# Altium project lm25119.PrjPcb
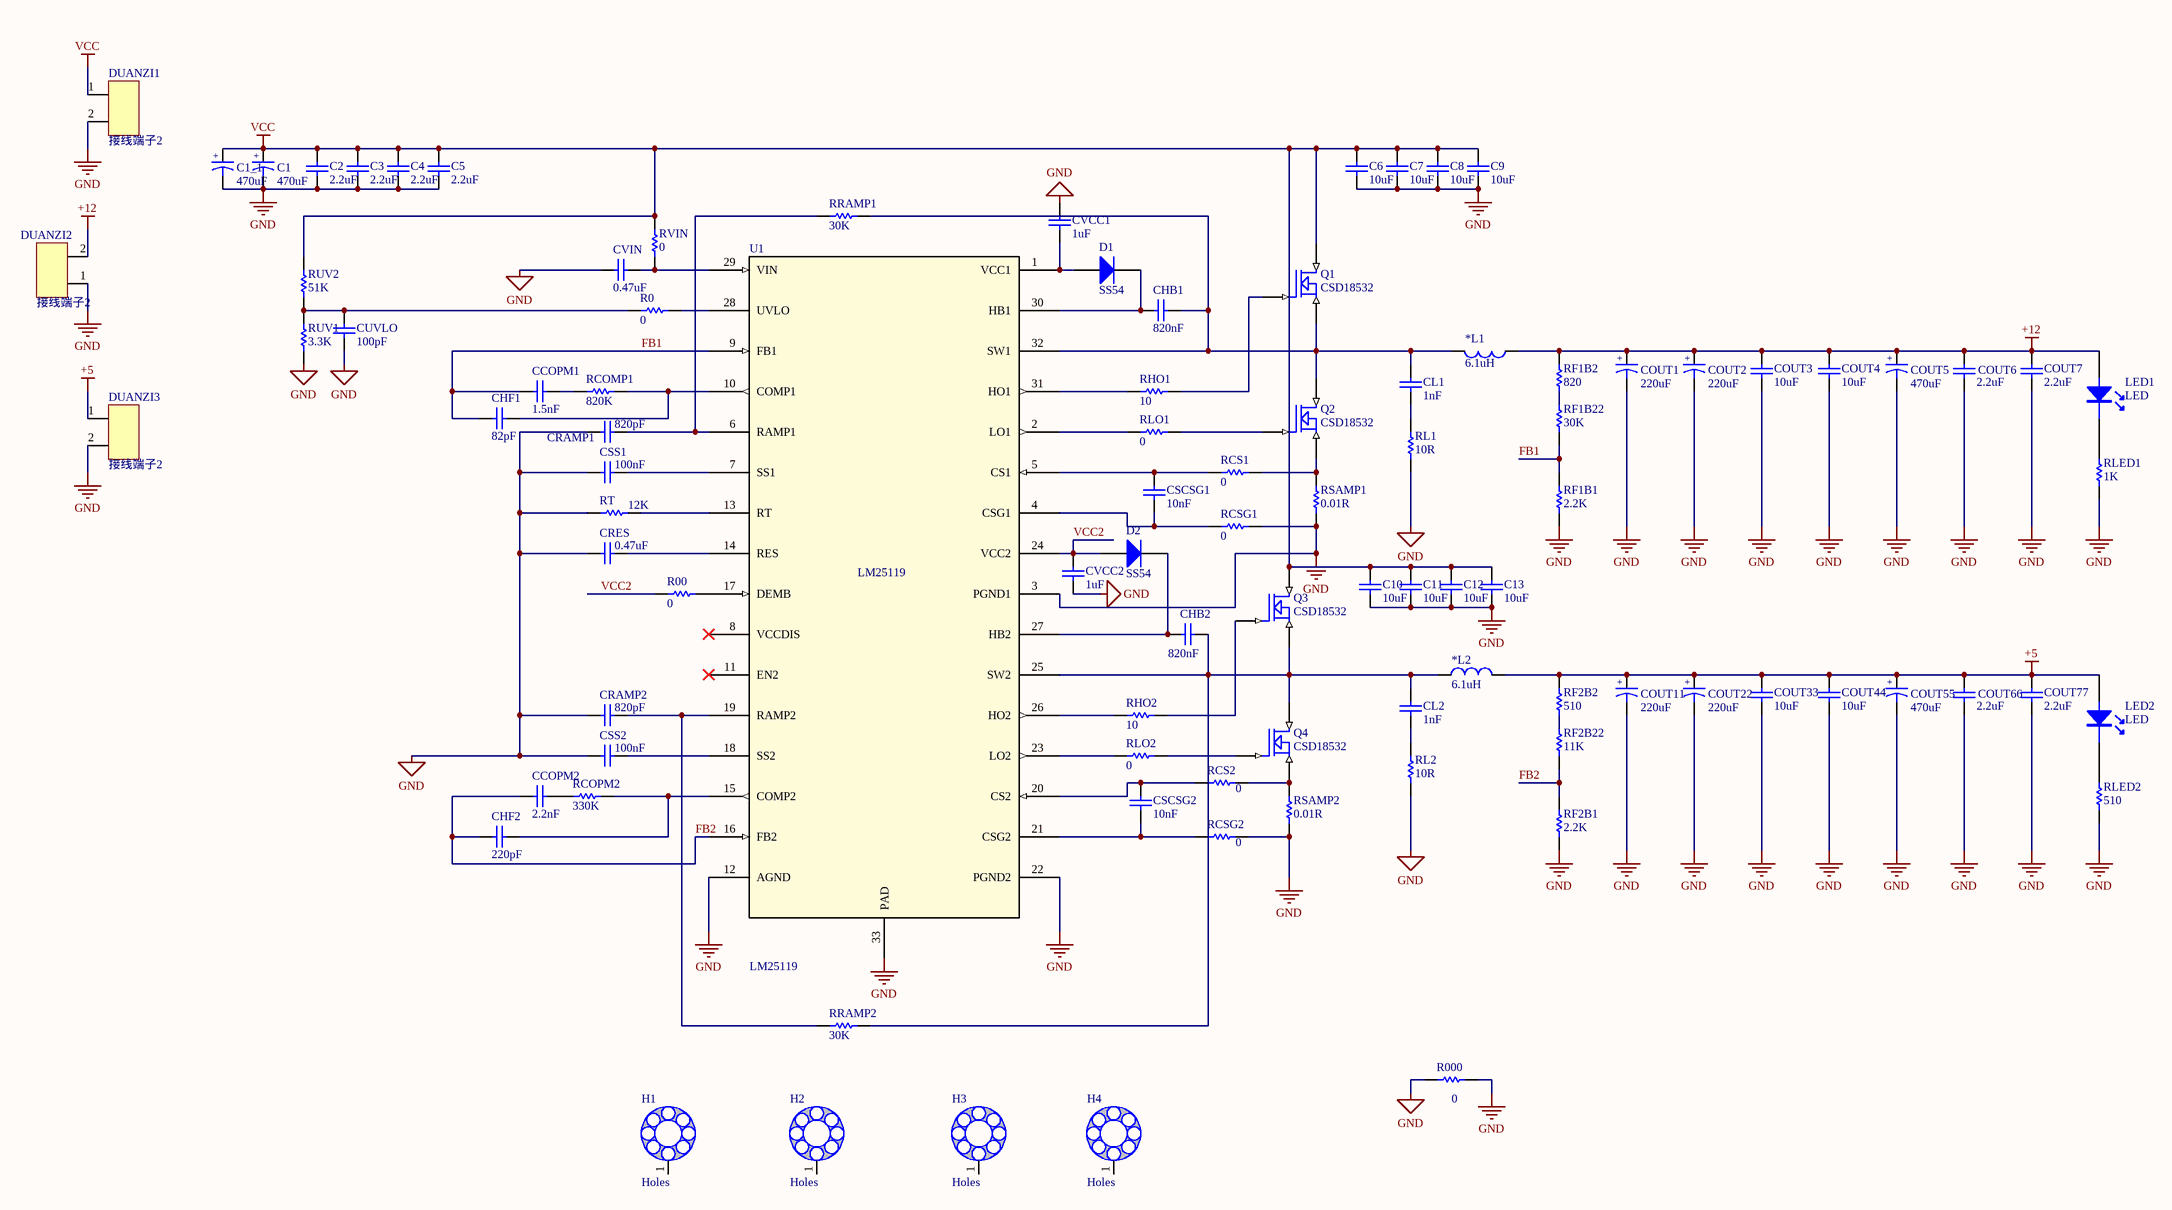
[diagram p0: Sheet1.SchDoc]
1 sheet, 96 parts. Net scope: global (net labels, ports and power ports of the same name join across sheets).
Board file: PCB1.PcbDoc

## Sheet Sheet1.SchDoc
size A2

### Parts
*L1  6.1uH  [CDEP147_6R1MS]
*L2  6.1uH  [CDEP147_6R1MS]
C1  470uF  [CD10]
C1_1  470uF  [CD10]
C2  2.2uF  [0805_c]
C3  2.2uF  [0805_c]
C4  2.2uF  [0805_c]
C5  2.2uF  [0805_c]
C6  10uF  [1206]
C7  10uF  [1206]
C8  10uF  [1206]
C9  10uF  [1206]
C10  10uF  [1206]
C11  10uF  [1206]
C12  10uF  [1206]
C13  10uF  [1206]
CCOPM1  1.5nF  [0805_c]
CCOPM2  2.2nF  [0805_c]
CHB1  820nF  [0805_c]
CHB2  820nF  [0805_c]
CHF1  82pF  [0805_c]
CHF2  220pF  [0805_c]
CL1  1nF  [0805_c]
CL2  1nF  [0805_c]
COUT1  220uF  [CD15]
COUT2  220uF  [CD15]
COUT3  10uF  [1206]
COUT4  10uF  [1206]
COUT5  470uF  [CD10]
COUT6  2.2uF  [0805_c]
COUT7  2.2uF  [0805_c]
COUT11  220uF  [CD15]
COUT22  220uF  [CD15]
COUT33  10uF  [1206]
COUT44  10uF  [1206]
COUT55  470uF  [CD10]
COUT66  2.2uF  [0805_c]
COUT77  2.2uF  [0805_c]
CRAMP1  820pF  [0805_c]
CRAMP2  820pF  [0805_c]
CRES  0.47uF  [0805_c]
CSCSG1  10nF  [0805_c]
CSCSG2  10nF  [0805_c]
CSS1  100nF  [0805_c]
CSS2  100nF  [0805_c]
CUVLO  100pF  [0805_c]
CVCC1  1uF  [0805_c]
CVCC2  1uF  [0805_c]
CVIN  0.47uF  [0805_c]
D1  SS54  [DO-214AC]
D2  SS54  [DO-214AC]
DUANZI1  接线端子2  [HB9500]
DUANZI2  接线端子2  [HB9500]
DUANZI3  接线端子2  [HB9500]
H1  Holes  [定位孔 Φ3 1]
H2  Holes  [定位孔 Φ3 1]
H3  Holes  [定位孔 Φ3 1]
H4  Holes  [定位孔 Φ3 1]
LED1  LED  [LED_small]
LED2  LED  [LED_small]
Q1  CSD18532  [TO220]
Q2  CSD18532  [TO220]
Q3  CSD18532  [TO220]
Q4  CSD18532  [TO220]
R0  0  [0805_r]
R00  0  [0805_r]
R000  0  [0805_r]
RCOMP1  820K  [0805_r]
RCOPM2  330K  [0805_r]
RCS1  0  [0805_r]
RCS2  0  [0805_r]
RCSG1  0  [0805_r]
RCSG2  0  [0805_r]
RF1B1  2.2K  [0805_r]
RF1B2  820  [0805_r]
RF1B22  30K  [0805_r]
RF2B1  2.2K  [0805_r]
RF2B2  510  [0805_r]
RF2B22  11K  [0805_r]
RHO1  10  [0805_r]
RHO2  10  [0805_r]
RL1  10R  [0805_r]
RL2  10R  [0805_r]
RLED1  1K  [0805_r]
RLED2  510  [0805_r]
RLO1  0  [0805_r]
RLO2  0  [0805_r]
RRAMP1  30K  [0805_r]
RRAMP2  30K  [0805_r]
RSAMP1  0.01R  [2512_R]
RSAMP2  0.01R  [2512_R]
RT  12K  [0805_r]
RUV1  3.3K  [0805_r]
RUV2  51K  [0805_r]
RVIN  0  [0805_r]
U1  LM25119  [WQFN]

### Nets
+5: *L2.2 COUT11.1 COUT22.1 COUT33.2 COUT44.2 COUT55.1 COUT66.2 COUT77.2 DUANZI3.1 LED2.1(A) RF2B2.2
+12: *L1.1 COUT1.1 COUT2.1 COUT3.2 COUT4.2 COUT5.1 COUT6.2 COUT7.2 DUANZI2.2 LED1.1(A) RF1B2.2
GND: C1.2 C1_1.2 C2.1 C3.1 C4.1 C5.1 C6.1 C7.1 C8.1 C9.1 C10.1 C11.1 C12.1 C13.1 COUT1.2 COUT2.2 COUT3.1 COUT4.1 COUT5.2 COUT6.1 COUT7.1 COUT11.2 COUT22.2 COUT33.1 COUT44.1 COUT55.2 COUT66.1 COUT77.1 CRAMP1.1 CRAMP2.2 CRES.1 CSS1.1 CSS2.2 CUVLO.1 CVCC1.1 CVCC2.1 CVIN.1 DUANZI1.2 DUANZI2.1 DUANZI3.2 R000.1 R000.2 RCSG1.2 RCSG2.2 RF1B1.1 RF2B1.1 RL1.1 RL2.1 RLED1.1 RLED2.1 RSAMP1.1 RSAMP2.1 RT.1 RUV1.1 U1.3(PGND1) U1.12(AGND) U1.22(PGND2) U1.33(PAD)
VCC: C1.1 C1_1.1 C2.2 C3.2 C4.2 C5.2 C6.2 C7.2 C8.2 C9.2 C10.2 C11.2 C12.2 C13.2 DUANZI1.1 Q1.2(D) Q3.2(D) RUV2.2 RVIN.2
FB1: CCOPM1.1 CHF1.1 RF1B1.2 RF1B22.1 U1.9(FB1)
FB2: CCOPM2.2 CHF2.2 RF2B1.2 RF2B22.1 U1.16(FB2)
VCC2: CVCC2.2 D2.1(A) R00.1 U1.24(VCC2)
Net*L1_2: *L1.2 CHB1.1 CL1.1 Q1.3(S) Q2.2(D) RRAMP1.2 U1.32(SW1)
Net*L2_1: *L2.1 CHB2.1 CL2.1 Q3.3(S) Q4.2(D) RRAMP2.1 U1.25(SW2)
NetCCOPM1_2: CCOPM1.2 RCOMP1.1
NetCCOPM2_1: CCOPM2.1 RCOPM2.2
NetCHB1_2: CHB1.2 D1.2(K) U1.30(HB1)
NetCHB2_2: CHB2.2 D2.2(K) U1.27(HB2)
NetCHF1_2: CHF1.2 RCOMP1.2 U1.10(COMP1)
NetCHF2_1: CHF2.1 RCOPM2.1 U1.15(COMP2)
NetCL1_2: CL1.2 RL1.2
NetCL2_2: CL2.2 RL2.2
NetCRAMP1_2: CRAMP1.2 RRAMP1.1 U1.6(RAMP1)
NetCRAMP2_1: CRAMP2.1 RRAMP2.2 U1.19(RAMP2)
NetCRES_2: CRES.2 U1.14(RES)
NetCSCSG1_1: CSCSG1.1 RCSG1.1 U1.4(CSG1)
NetCSCSG1_2: CSCSG1.2 RCS1.1 U1.5(CS1)
NetCSCSG2_1: CSCSG2.1 RCSG2.1 U1.21(CSG2)
NetCSCSG2_2: CSCSG2.2 RCS2.1 U1.20(CS2)
NetCSS1_2: CSS1.2 U1.7(SS1)
NetCSS2_1: CSS2.1 U1.18(SS2)
NetCUVLO_2: CUVLO.2 R0.1 RUV1.2 RUV2.1
NetCVCC1_2: CVCC1.2 D1.1(A) U1.1(VCC1)
NetCVIN_2: CVIN.2 RVIN.1 U1.29(VIN)
NetLED1_2: LED1.2(K) RLED1.2
NetLED2_2: LED2.2(K) RLED2.2
NetQ1_1: Q1.1(G) RHO1.2
NetQ2_1: Q2.1(G) RLO1.2
NetQ2_3: Q2.3(S) RCS1.2 RSAMP1.2
NetQ3_1: Q3.1(G) RHO2.2
NetQ4_1: Q4.1(G) RLO2.2
NetQ4_3: Q4.3(S) RCS2.2 RSAMP2.2
NetR00_2: R00.2 U1.17(DEMB)
NetR0_2: R0.2 U1.28(UVLO)
NetRF1B2_1: RF1B2.1 RF1B22.2
NetRF2B2_1: RF2B2.1 RF2B22.2
NetRHO1_1: RHO1.1 U1.31(HO1)
NetRHO2_1: RHO2.1 U1.26(HO2)
NetRLO1_1: RLO1.1 U1.2(LO1)
NetRLO2_1: RLO2.1 U1.23(LO2)
NetRT_2: RT.2 U1.13(RT)

Not connected (* = marked no-connect by the designer): H1 1; H2 1; H3 1; H4 1; U1 8(VCCDIS)* 11(EN2)*

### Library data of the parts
*L1 *L2 = L_三端大电流电感
C1 C1_1 COUT1 COUT2 COUT5 COUT11 COUT22 COUT55 = CAP1
C2-C13 CCOPM1 CCOPM2 CHB1 CHB2 CHF1 CHF2 CL1 CL2 COUT3 COUT4 COUT6 COUT7 COUT33 COUT44 COUT66 COUT77 CRAMP1 CRAMP2 CRES CSCSG1 CSCSG2 CSS1 CSS2 CUVLO CVCC1 CVCC2 CVIN = CAP: Capacitor; Value: 104
D1 D2 = 1N4007: High Conductance Fast Diode
H1-H4 = Holes: holes in the corner of the bord
LED1 LED2 = LED1
Q1-Q4 = MOSFET N
R0 R00 R000 RCOMP1 RCOPM2 RCS1 RCS2 RCSG1 RCSG2 RF1B1 RF1B2 RF1B22 RF2B1 RF2B2 RF2B22 RHO1 RHO2 RL1 RL2 RLED2 RLO1 RLO2 RRAMP1 RRAMP2 RSAMP1 RSAMP2 RT RUV1 RUV2 RVIN = RES: Resistor; Value: 1K
RLED1 = RES: Resistor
